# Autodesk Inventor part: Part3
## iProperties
Shininess: 77.0
Angle Display Precision: 2
Document Length Units: 11269
Document Angle Units: 11279
Document Time Units: 11290
Document Mass Units: 11283
Document Length Units Precision: 3
Document Angle Units Precision: 2
Compacted: True
Created: 2001-12
Part Number: Part3
Document SubType Name: Modeling
Designer: Renu Muthoo
Density: 0.0
Volumn: 0.0
Area: 0.0
PropertySet Name: Model Information
Control State: 0
Master: False
Checked Out: False
Author: Renu Muthoo
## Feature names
1. Revolution2
2. Extrusion1
